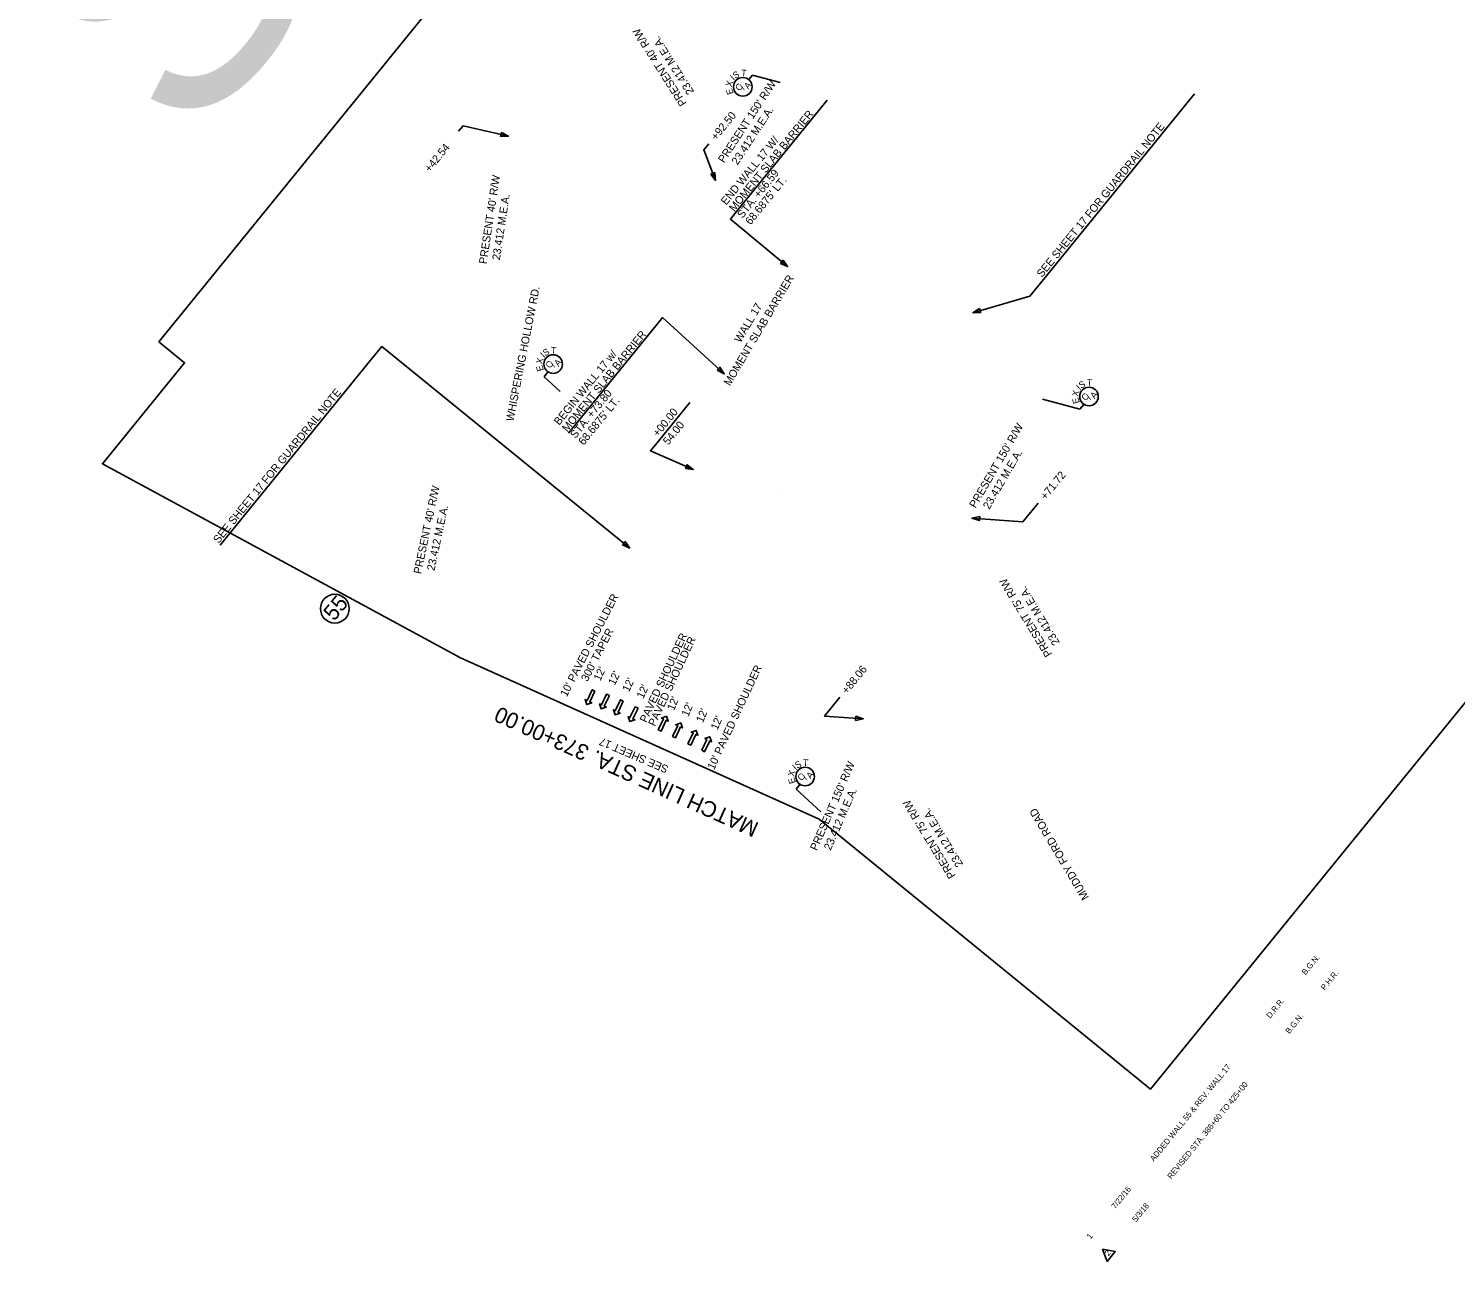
# Model space of a CAD drawing. Extents: x 1615766 to 1617965, y 1099429 to 1101416.
# Drawn here: x 1615766 to 1616854, y 1099429 to 1100369 of the extents above; entities that cross this region are included whole.
import ezdxf

# ---------------------------------------------------------------- set-up
doc = ezdxf.new("R2010")
doc.units = 0
for name, color, linetype in [('FH_Plot_Shape', 7, 'Continuous'), ('RD_EX_Bldg', 7, 'Continuous'), ('RD_EX_Conc', 7, 'Continuous'), ('RD_EX_Driveway', 7, 'Continuous'), ('RD_EX_DV_TX_Gov', 7, 'Continuous'), ('RD_EX_Fence_ChLk', 7, 'Continuous'), ('RD_EX_H2O_WetLd', 7, 'Continuous'), ('RD_EX_Misc_Golf_Teebox', 7, 'Continuous'), ('RD_EX_Road', 7, 'Continuous'), ('RD_EX_VEG', 7, 'Continuous')]:
    doc.layers.add(name, color=color, linetype=linetype)

msp = doc.modelspace()

# ---------------------------------------------------------------- linework, layer by layer
at = {"layer": 'FH_Plot_Shape'}
msp.add_circle((1615999.2, 1099926.3), 11, dxfattribs=at)
at = {"layer": 'RD_EX_Bldg'}
for points in [[(1616197.7, 1099863.5), (1616195.6, 1099864.5), (1616191.6, 1099856.2), (1616190.1, 1099856.9), (1616191.5, 1099853.1), (1616195.2, 1099854.5), (1616193.8, 1099855.2)], [(1616208.8, 1099860.2), (1616206.6, 1099861.2), (1616202.7, 1099852.9), (1616201.2, 1099853.6), (1616202.5, 1099849.9), (1616206.3, 1099851.2), (1616204.8, 1099851.9)], [(1616219.2, 1099855.7), (1616217.1, 1099856.8), (1616213.1, 1099848.5), (1616211.7, 1099849.2), (1616213, 1099845.4), (1616216.8, 1099846.7), (1616215.3, 1099847.4)], [(1616219.2, 1099855.7), (1616217.1, 1099856.8), (1616213.1, 1099848.5), (1616211.7, 1099849.2), (1616213, 1099845.4), (1616216.8, 1099846.7), (1616215.3, 1099847.4)], [(1616230.6, 1099850.5), (1616228.4, 1099851.5), (1616224.4, 1099843.2), (1616223, 1099843.9), (1616224.3, 1099840.2), (1616228.1, 1099841.5), (1616226.6, 1099842.2)], [(1616230.6, 1099850.5), (1616228.4, 1099851.5), (1616224.4, 1099843.2), (1616223, 1099843.9), (1616224.3, 1099840.2), (1616228.1, 1099841.5), (1616226.6, 1099842.2)], [(1616246, 1099833.9), (1616248.2, 1099832.9), (1616252.1, 1099841.2), (1616253.6, 1099840.5), (1616252.2, 1099844.2), (1616248.4, 1099842.9), (1616249.9, 1099842.2)], [(1616256.9, 1099828.8), (1616259.1, 1099827.8), (1616263, 1099836.1), (1616264.4, 1099835.4), (1616263.1, 1099839.2), (1616259.3, 1099837.8), (1616260.8, 1099837.1)], [(1616268.6, 1099823.2), (1616270.8, 1099822.1), (1616274.7, 1099830.4), (1616276.2, 1099829.7), (1616274.9, 1099833.5), (1616271.1, 1099832.2), (1616272.6, 1099831.5)], [(1616279.1, 1099818.3), (1616281.2, 1099817.2), (1616285.2, 1099825.5), (1616286.6, 1099824.8), (1616285.3, 1099828.6), (1616281.5, 1099827.2), (1616283, 1099826.5)]]:
    msp.add_lwpolyline(points, close=True, dxfattribs=at)
at = {"layer": 'RD_EX_Conc'}
for points in [[(1616093.6, 1100290.3), (1616097, 1100294.5), (1616131.7, 1100286.5)], [(1616284.5, 1100280.7), (1616280.7, 1100276.1), (1616289.7, 1100252.8)], [(1616535.7, 1100006.8), (1616524.2, 1099992.6), (1616485.3, 1099995.4)], [(1616384.6, 1099858.7), (1616372.9, 1099844.4), (1616402.3, 1099842.3)]]:
    msp.add_lwpolyline(points, dxfattribs=at)
for points in [[(1616125.7, 1100286.3), (1616131.7, 1100286.5), (1616126.4, 1100289.3)], [(1616286.1, 1100257.6), (1616289.7, 1100252.8), (1616289, 1100258.8)], [(1616491.2, 1099996.5), (1616485.3, 1099995.4), (1616491, 1099993.4)], [(1616396.4, 1099841.1), (1616402.3, 1099842.3), (1616396.7, 1099844.2)]]:
    msp.add_lwpolyline(points, close=True, dxfattribs=at)
at = {"layer": 'RD_EX_Driveway'}
for p, q in [((1616655, 1100318.8), (1616539.9, 1100177.4)), ((1616026.8, 1100116.1), (1615911.7, 1099974.7))]:
    msp.add_line(p, q, dxfattribs=at)
for points in [[(1616539.9, 1100177.4), (1616529.5, 1100164.6), (1616486, 1100152)], [(1616026.8, 1100116.1), (1616035.1, 1100126.3), (1616224.2, 1099972.5)]]:
    msp.add_lwpolyline(points, dxfattribs=at)
for points in [[(1616491.1, 1100155.1), (1616486, 1100152), (1616492, 1100152.2)], [(1616218.7, 1099975), (1616224.2, 1099972.5), (1616220.7, 1099977.4)]]:
    msp.add_lwpolyline(points, close=True, dxfattribs=at)
at = {"layer": 'RD_EX_DV_TX_Gov'}
for p, q in [((1616315, 1100329.7), (1616317.8, 1100333.2)), ((1616317.8, 1100333.2), (1616339, 1100327.6)), ((1616158.9, 1100103.2), (1616161.8, 1100106.8)), ((1616158.9, 1100103.2), (1616171, 1100091.9)), ((1616567.7, 1100078.5), (1616539.2, 1100086)), ((1616567.7, 1100078.5), (1616570.6, 1100082.1)), ((1616351.1, 1099788.7), (1616354, 1099792.3)), ((1616351.1, 1099788.7), (1616370.1, 1099771.4))]:
    msp.add_line(p, q, dxfattribs=at)
for centre in [(1616310.5, 1100324.2), (1616165.8, 1100112.8), (1616574.6, 1100088.1), (1616358, 1099798.3)]:
    msp.add_circle(centre, 7.08, dxfattribs=at)
at = {"layer": 'RD_EX_Fence_ChLk'}
msp.add_lwpolyline([(1616368.7, 1099765.8), (1616621.6, 1099560), (1617489.2, 1100625.8), (1617256.2, 1100856.1), (1617080.1, 1101099), (1616848.9, 1101284.7), (1616739.1, 1101147.9), (1616711.3, 1101170.2), (1615865, 1100129.8), (1615884.6, 1100113.8), (1615821.9, 1100036.8), (1616095.1, 1099888.9)], close=True, dxfattribs=at)
msp.add_lwpolyline([(1616368.7, 1099765.8), (1616621.6, 1099560), (1617489.2, 1100625.8), (1617256.2, 1100856.1), (1617080.1, 1101099), (1616848.9, 1101284.7), (1616739.1, 1101147.9), (1616711.3, 1101170.2), (1615865, 1100129.8), (1615884.6, 1100113.8), (1615821.9, 1100036.8), (1616095.1, 1099888.9)], close=True, dxfattribs=at)
at = {"layer": 'RD_EX_Misc_Golf_Teebox'}
for p, q in [((1616374.8, 1100314), (1616304.7, 1100227.9)), ((1616247.4, 1100146), (1616177.4, 1100060)), ((1616270, 1100083.4), (1616246.1, 1100054.1)), ((1616339.2, 1100016.2), (1616339.2, 1100016.2))]:
    msp.add_line(p, q, dxfattribs=at)
for points in [[(1616304.7, 1100227.9), (1616301, 1100223.4), (1616344.6, 1100187.1)], [(1616247.4, 1100146), (1616249.2, 1100148.2), (1616296.3, 1100105.3)], [(1616246.1, 1100054.1), (1616240, 1100046.6), (1616272.6, 1100032.3)]]:
    msp.add_lwpolyline(points, dxfattribs=at)
for points in [[(1616339.2, 1100189.6), (1616344.6, 1100187.1), (1616341.2, 1100192)], [(1616290.9, 1100108.1), (1616296.3, 1100105.3), (1616293, 1100110.4)], [(1616266.7, 1100033.2), (1616272.6, 1100032.3), (1616268, 1100036)], [(1616584.8, 1099437.8), (1616588.5, 1099428.5), (1616594.6, 1099436)]]:
    msp.add_lwpolyline(points, close=True, dxfattribs=at)
at = {"layer": 'RD_EX_VEG'}
msp.add_lwpolyline([(1616368.7, 1099765.8), (1616231.9, 1099827.4), (1616095.1, 1099888.9)], dxfattribs=at)

# ---------------------------------------------------------------- texts
at = {"layer": 'FH_Plot_Shape'}
msp.add_text('55', height=12, rotation=50.3033, dxfattribs=at).set_placement((1615998.7, 1099916.3))
at = {"layer": 'RD_EX_Conc'}
for s, rotation, p in [("PRESENT 40' R/W ", 122.4258, (1616267.9, 1100311.8)), ('  23.412 M.E.A.', 122.4258, (1616275.9, 1100316.8)), ("PRESENT 150' R/W ", 56.6756, (1616296.1, 1100265.7)), ('+92.50', 50.8545, (1616290.2, 1100283)), ('  23.412 M.E.A.', 56.6756, (1616304, 1100260.5)), ('+42.54', 50.8545, (1616071.7, 1100258.7)), ("PRESENT 40' R/W ", 81.3291, (1616115, 1100188.8)), ('  23.412 M.E.A.', 81.3291, (1616124.4, 1100187.4)), ("PRESENT 150' R/W ", 59.7383, (1616488, 1100002.5)), ('  23.412 M.E.A.', 59.7383, (1616496.2, 1099997.7)), ('+71.72', 50.8545, (1616541.6, 1100008.8)), ("PRESENT 40' R/W ", 78.0227, (1616065, 1099952.4)), ('  23.412 M.E.A.', 78.0227, (1616074.3, 1099950.5)), ("PRESENT 75' R/W ", 121.3586, (1616546.7, 1099891.7)), ('  23.412 M.E.A.', 121.3586, (1616554.8, 1099896.7)), ('+88.06', 50.8545, (1616390, 1099860.7)), ("PRESENT 150' R/W ", 66.4442, (1616367, 1099741.3)), ('  23.412 M.E.A.', 66.4442, (1616375.7, 1099737.5)), ("PRESENT 75' R/W ", 121.3586, (1616473, 1099722.7)), ('  23.412 M.E.A.', 121.3586, (1616481.1, 1099727.6))]:
    msp.add_text(s, height=6, rotation=rotation, dxfattribs=at).set_placement(p)
at = {"layer": 'RD_EX_Driveway'}
for p in [(1616538.7, 1100178.4), (1615910.5, 1099975.6)]:
    msp.add_text('SEE SHEET 17 FOR GUARDRAIL NOTE', height=6, rotation=50.8545, dxfattribs=at).set_placement(p)
at = {"layer": 'RD_EX_DV_TX_Gov'}
for s, rotation, p in [('I', 40.7866, (1616303.4, 1100328.8)), ('S', 29.0661, (1616304.5, 1100330.1)), ('T', 353.9046, (1616309, 1100332.5)), ('X', 75.948, (1616302.1, 1100323.9)), ('E', 109.4352, (1616303.6, 1100319.3)), ('C', 50.8513, (1616308, 1100320.6)), ('/', 50.8513, (1616311.5, 1100321.5)), ('A', 50.8513, (1616314.7, 1100322)), ('X', 75.948, (1616157.4, 1100112.5)), ('I', 41.9028, (1616158.7, 1100117.3)), ('S', 30.1823, (1616159.7, 1100118.6)), ('T', 356.6952, (1616164, 1100121)), ('A', 50.8513, (1616169.9, 1100110.6)), ('E', 107.7608, (1616158.7, 1100108.2)), ('C', 50.8513, (1616163.3, 1100109.1)), ('/', 50.8513, (1616166.8, 1100110.1)), ('I', 41.9028, (1616567.5, 1100092.6)), ('S', 30.1823, (1616568.6, 1100093.9)), ('T', 356.6952, (1616572.8, 1100096.3)), ('X', 75.948, (1616566.2, 1100087.8)), ('E', 107.7608, (1616567.6, 1100083.5)), ('C', 50.8513, (1616572.1, 1100084.4)), ('/', 50.8513, (1616575.7, 1100085.4)), ('A', 50.8513, (1616578.8, 1100085.9)), ('T', 356.6952, (1616356.2, 1099806.5)), ('X', 75.948, (1616349.6, 1099798)), ('I', 41.9028, (1616350.9, 1099802.8)), ('S', 30.1823, (1616352, 1099804.1)), ('C', 50.8513, (1616355.5, 1099794.6)), ('/', 50.8513, (1616359, 1099795.6)), ('A', 50.8513, (1616362.2, 1099796.1)), ('E', 107.7608, (1616351, 1099793.7))]:
    msp.add_text(s, height=5, rotation=rotation, dxfattribs=at).set_placement(p)
at = {"layer": 'RD_EX_H2O_WetLd'}
for s, rotation, p in [('WHISPERING HOLLOW RD.', 78.9276, (1616135.5, 1100068.8)), ('MUDDY FORD ROAD', 120.8188, (1616574.8, 1099706.3))]:
    msp.add_text(s, height=6, rotation=rotation, dxfattribs=at).set_placement(p)
at = {"layer": 'RD_EX_Misc_Golf_Teebox'}
for s, height, rotation, p in [('MOMENT SLAB BARRIER', 6, 50.8561, (1616304, 1100228.6)), ('END WALL 17 W/', 6, 50.8561, (1616297.8, 1100233.6)), ('STA. +66.59', 6, 50.8561, (1616310.2, 1100223.5)), ("68.6875' LT.", 6, 50.8561, (1616316.4, 1100218.5)), ('MOMENT SLAB BARRIER', 6, 59.3765, (1616300.7, 1100095.7)), ('WALL 17', 6, 59.3765, (1616308.7, 1100128.6)), ('MOMENT SLAB BARRIER', 6, 50.8561, (1616176.6, 1100060.6)), ('BEGIN WALL 17 w/', 6, 50.8561, (1616170.4, 1100065.7)), ('STA. +73.80', 6, 50.8561, (1616182.8, 1100055.6)), ("68.6875' LT.", 6, 50.8561, (1616189.1, 1100050.5)), ('+00.00', 6, 50.8545, (1616245.8, 1100056.9)), ('54.00', 6, 50.8545, (1616253.6, 1100050.6)), ("10' PAVED SHOULDER", 6, 62.7318, (1616176.1, 1099858.6)), ("300' TAPER", 6, 62.7318, (1616192, 1099870.3)), (' PAVED SHOULDER', 6, 64.94, (1616236, 1099836.9)), (' PAVED SHOULDER', 6, 64.94, (1616242.5, 1099834.1)), ("12'", 6, 64.7845, (1616201.7, 1099870.7)), ("12'", 6, 64.7845, (1616212.8, 1099867.4)), ("10' PAVED SHOULDER", 6, 64.94, (1616288.5, 1099803)), ("12'", 6, 64.7845, (1616223.6, 1099862.3)), ("12'", 6, 64.7845, (1616234.5, 1099857.2)), ("12'", 6, 67.3291, (1616257.9, 1099848.1)), ("12'", 6, 67.3291, (1616268.9, 1099843.5)), ("12'", 6, 67.3291, (1616280, 1099838.9)), ("12'", 6, 67.3291, (1616291.2, 1099833.3)), ('B.G.N.', 4.4, 50.8545, (1616739.8, 1099646.6)), ('P.H.R.', 4.4, 50.8545, (1616754.4, 1099634.9)), ('D.R.R.', 4.4, 50.8545, (1616712.9, 1099613.5)), ('B.G.N.', 4.4, 50.8545, (1616727.4, 1099601.7)), ('ADDED WALL 55 & REV. WALL 17', 4.4, 50.8545, (1616624.1, 1099504.4)), ('REVISED STA. 386+60 TO 425+00', 4.4, 50.8545, (1616637.3, 1099491)), ('7/22/16', 4.4, 50.8545, (1616594.6, 1099468.2)), ('5/3/18', 4.4, 50.8545, (1616610.5, 1099458.1)), ('1', 4.4, 50.8545, (1616575.8, 1099445.1)), ('2', 4.4, 50.8545, (1616589.5, 1099432.3))]:
    msp.add_text(s, height=height, rotation=rotation, dxfattribs=at).set_placement(p)
at = {"layer": 'RD_EX_Road'}
msp.add_text('SHEET 18', height=200, rotation=50.8545, dxfattribs=at).set_placement((1615888.3, 1100275.4))
at = {"layer": 'RD_EX_VEG'}
for s, height, rotation, p in [('MATCH LINE STA. 373+00.00', 12, 155.7736, (1616323.5, 1099762.6)), ('SEE SHEET 17', 6, 156.8359, (1616254.3, 1099806.1))]:
    msp.add_text(s, height=height, rotation=rotation, dxfattribs=at).set_placement(p)

doc.saveas('drawing.dxf')
